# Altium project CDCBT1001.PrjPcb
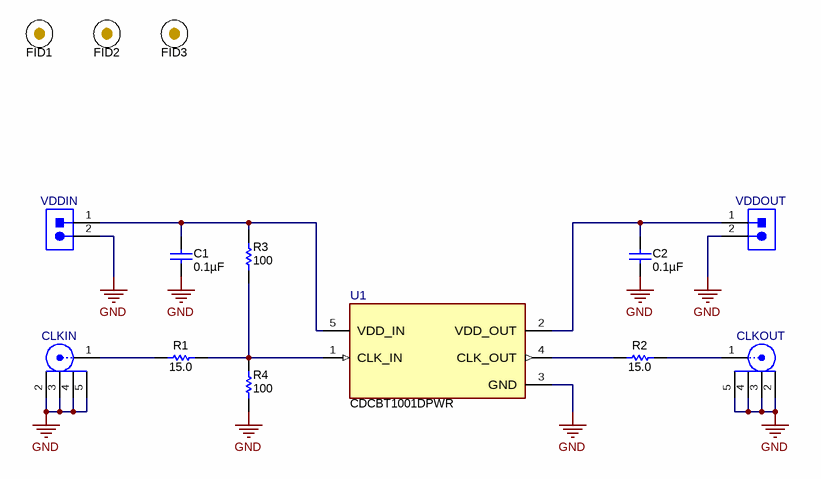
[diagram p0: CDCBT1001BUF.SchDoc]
TID: N/A; TechSupport: http://www.ti.com/support; SCH_Rev: A; PRJ_Title: CDCBT1001 EVM; PRJ_Customer: Public Release; PCB_Rev: A; CopyrightYear: 2022
1 sheet, 14 parts. Net scope: global (net labels, ports and power ports of the same name join across sheets).
Board file: CDCBT1001.PcbDoc

## Sheet CDCBT1001BUF.SchDoc: Buffer
size Letter; Date: Not shown in title block; ApprovedBy: Not shown in title block; CheckedBy: Not shown in title block; Author: Not shown in title block; CompanyName: Not shown in title block; DrawnBy: Noel Fung; Engineer: Not shown in title block; Organization: Not shown in title block; Address1: Not shown in title block; Address2: Not shown in title block; Address3: Not shown in title block; Address4: Not shown in title block; DocumentNumber: 2; Revision: Use project parameter SCH_Rev; SheetNumber: 1; SheetTotal: 2; PageSetup: Record=PageOptions¦CenterHorizontal=True¦CenterVertical=True¦PrintScale=1.00¦XCorrection=1.00¦YCorrection=1.00¦PrintKind=0¦BorderSize=5000000¦LeftOffset=0¦BottomOffset=0¦Orientation=2¦PaperLength=1000¦PaperWidth=1000¦Scale=100¦PaperSource=15¦PrintQuality=600¦MediaType=1¦DitherType=10¦PaperKind=Letter¦PrintScaleMode=1

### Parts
C1  ValueDisplayed: 0.1µF  [0402S]  (hidden comment: 885012205037)
C2  ValueDisplayed: 0.1µF  [0402S]  (hidden comment: 885012205037)
FID1  Fiducial  [Fiducial10-20]  (value not drawn)
FID2  Fiducial  [Fiducial10-20]  (value not drawn)
FID3  Fiducial  [Fiducial10-20]  (value not drawn)
J1  VDDIN  [TSW-102-07-G-S]
J2  VDDOUT  [TSW-102-07-G-S]
J3  CLKIN  [Emerson_142-0701-851]
J4  CLKOUT  [Emerson_142-0701-851]
R1  ValueDisplayed: 15.0  [0402S]  (hidden comment: CRCW040215R0FKED)
R2  ValueDisplayed: 15.0  [0402S]  (hidden comment: CRCW040215R0FKED)
R3  ValueDisplayed: 100  [0402S]  (hidden comment: CRCW0402100RFKED)
R4  ValueDisplayed: 100  [0402S]  (hidden comment: CRCW0402100RFKED)
U1  CDCBT1001DPWR  [DPW0005A-MFG]

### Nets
GND: C1.2 C2.2 J1.2 J2.2 J3.2 J3.3 J3.4 J3.5 J4.2 J4.3 J4.4 J4.5 R4.1 U1.3(GND)
NetC1_1: C1.1 J1.1 R3.2 U1.5(VDD_IN)
NetC2_1: C2.1 J2.1 U1.2(VDD_OUT)
NetJ3_1: J3.1 R1.1
NetJ4_1: J4.1 R2.2
NetR1_2: R1.2 R3.1 R4.2 U1.1(CLK_IN)
NetR2_1: R2.1 U1.4(CLK_OUT)

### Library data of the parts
C1 C2 = CMP-0006228-2: CAP, CERM, 0.1 uF, 16 V, +/- 10%, X7R, 0402; Manufacturer: Wurth Elektronik; TaMin_C: -55°C; Polarized: N; SizeAreaWB_mm2: 3; Value1: Unknown; U/M: EA; Value: 0.1µF; TaMax_C: 125°C; SizeZ_mm: 0.6; SizeX_mm: 1; SizeY_mm: 0.5; Cap_Case: 0402; Value2: 16V; Cap_F: 100nF; AEC Category: Q200
FID1-FID3 = CMP-0077181-1: Fiducial mark.  There is nothing to buy or mount.
J1 J2 = CMP-0075405-3: Header, 100mil, 2x1, Gold, TH; Manufacturer: Samtec; Current_A: 6.3A; Green_Lifecycle: Active; Pitch_mm: 2.54; Cert_CSA: Y; Cert_VDE: N; Green_REACh: Passed; Row_Count: 1; Gender: Male; Voltage_V: 550V
J3 J4 = CMP-0055822-3: Connector, End launch SMA, 50 ohm, SMT; Manufacturer: Cinch Connectivity; PartNumber: 142-0701-851; Green_Lifecycle: Not Set; Green_REACh: Incomplete
R1 R2 = CMP-0026030-3: RES, 15.0, 1%, 0.063 W, AEC-Q200 Grade 0, 0402; Manufacturer: Vishay-Dale; Power_W: 63mW; TempCo: 100 ppm/C; Value_Code: 15R0; Value: 15.0; EIA_Code: E96; Res_ohm: 15; SizeX_mm: 1; SizeY_mm: 0.5; SizeZ_mm: 0.6; Value2: 0.063W; AEC Qualified: Y; VDC_V: 50V; AEC Category: Q200; AEC Grade: 0
R3 R4 = CMP-0025951-3: RES, 100, 1%, 0.063 W, AEC-Q200 Grade 0, 0402; Manufacturer: Vishay-Dale; Power_W: 63mW; TempCo: 100 ppm/C; Value_Code: 100R; Value: 100; EIA_Code: E96; SizeX_mm: 1; SizeY_mm: 0.5; SizeZ_mm: 0.6; Value2: 0.063W; AEC Qualified: Y; VDC_V: 50V; AEC Category: Q200; AEC Grade: 0
U1 = CMP-0094493-1: 1.2 to 1.8-V Clock Buffer And Level Translator; Manufacturer: Texas Instruments; TaMax_C: +85°C; Standoff Height: 0mm; Logic Function Desc: Non-Inverting; TaMin_C: -40°C; AEC Qualified: No; PositionCount: 1; V A Max: 1.32V; Propagation Delay: 10ns; V B Max: 1.98V; SizeZ_mm: 0.4mm; Frequency_Fixed: 24MHz; TJmax_C: +150°C; V B Min: 1.62V; V A Min: 1.08V

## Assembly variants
001: not fitted FID1 FID2 FID3 R3 R4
